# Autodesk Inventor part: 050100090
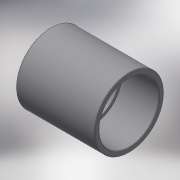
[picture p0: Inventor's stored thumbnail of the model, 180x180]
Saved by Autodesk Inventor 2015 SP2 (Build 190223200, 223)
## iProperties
Created: 2017-10
Part Number: 050100090
Material: Generic
Description: PLASSON SOCKET PVC 90 - CEMENT
Document SubType Name: Modeling
Designer: KIM
Density: 1 g/cm^3
Appearance: Default
Author: KIM
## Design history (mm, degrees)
derived "050100.ipt"
feature "Solid1::050100.ipt"
tag "TaggingFeature1"
body "Solid1"
other parameters: "d0" = 108, "d1" = 104, "d2" = 51, "d3" = 6, "d5" = 81, "d7" = 0.9, "E_" = 104, "H_" = 108, "l_" = 51, "Z_" = 6
